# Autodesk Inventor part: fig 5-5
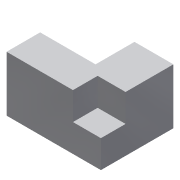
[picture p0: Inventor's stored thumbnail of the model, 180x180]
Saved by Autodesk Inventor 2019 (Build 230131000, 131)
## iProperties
Created: 2010-02
Part Number: fig 5-5
Document SubType Name: Modeling
Designer: CADSoft
Density: 1 g/cm^3
Material: Generic
Appearance: Default
Author: CADSoft
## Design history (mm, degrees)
sketch "Sketch1"
  geometry: L1 (0, 26.227)-(0, 12.145); L2 (0, 12.145)-(-20.026, 12.145); L3 (-20.026, 12.145)-(-20.026, 0); L4 (-20.026, 0)-(14.083, 0); L5 (14.083, 0)-(14.083, 26.227); L6 (14.083, 26.227)-(0, 26.227); 1 further point
  constraints: 12 end point
extrude "Extrusion1" new body sketch "Sketch1" distance "d0" = 20; taper "d1" = 0 deg
sketch "Sketch2"
  geometry: L1 (14.083, 0)-(3.983, 0); L2 (3.983, 0)-(3.983, 8.922); L3 (3.983, 8.922)-(14.083, 8.922); L4 (14.083, 8.922)-(14.083, 0); 1 further point
  constraints: 8 end point
extrude "Extrusion2" cut sketch "Sketch2" distance "d2" = 10; taper "d3" = 0 deg
body "Solid1"
